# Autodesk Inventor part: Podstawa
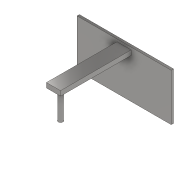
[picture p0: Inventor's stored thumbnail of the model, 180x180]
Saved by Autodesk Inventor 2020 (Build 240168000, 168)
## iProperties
Created: 2021-01
Part Number: Podstawa
Material: Stal, węglowa
Document SubType Name: Modeling
Designer: Home
Mass: 1175.24 g
Surface Area: 568.85 cm^2
Volume: 149.712 cm^3
Density: 7.85 g/cm^3
Appearance: Częściowo polerowany
Author: Home
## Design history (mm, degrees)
sketch "Szkic1"
  geometry: L1 (-100, -50)-(100, -50); L2 (100, -50)-(100, 50); L3 (100, 50)-(-100, 50); L4 (-100, 50)-(-100, -50); L5 (-100, -50)-(100, 50); L6 (100, -50)-(-100, 50); 1 further point
  constraints: 12 end point, 2 midpoint, 2 parallel, 1 horizontal, 1 perpendicular
  dimensions: "d0" = 200 distance of L3.end L2.end; "d1" = 100 distance of L2.end L1.end
extrude "Wyciągnięcie proste1" new body sketch "Szkic1" distance "d2" = 5; taper "d3" = 0 deg
sketch "Szkic2"
  geometry: L1 (-15, 35)-(15, 35); L2 (15, 35)-(15, 45); L3 (15, 45)-(-15, 45); L4 (-15, 45)-(-15, 35); L5 (-15, 35)-(15, 45); L6 (15, 35)-(-15, 45); 3 further points
  constraints: 12 end point, 3 midpoint, 2 parallel, 1 horizontal, 1 perpendicular, 1 vertical alignment
  dimensions: "d4" = 10 distance of L1.end L2.end; "d5" = 30 distance of L2.end L3.end; "d6" = 35 distance from line of point (0, 0) L1
extrude "Wyciągnięcie proste2" join sketch "Szkic2" distance "d7" = 150; taper "d8" = 0 deg
sketch "Szkic3"
  geometry: L1 (-85, 0)-(115, 0) reference; L2 (0, 150)-(30, 150) reference; C1 r 5 at (15, 135); 2 further points
  constraints: 1 centre point, 1 midpoint, 1 vertical alignment
  dimensions: "d9" = 10 diameter of C1; "d10" = 15 distance from line of L2 C1.centre
extrude "Wyciągnięcie proste3" join sketch "Szkic3" distance "d11" = 60; taper "d12" = 0 deg
node "Bryła1"
